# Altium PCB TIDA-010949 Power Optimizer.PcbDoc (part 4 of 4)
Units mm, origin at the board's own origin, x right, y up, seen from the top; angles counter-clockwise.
Board outline 129.4 x 84 mm, 4 copper layers (Power1, Ground1, Ground2, Power2), stack 1.926 mm thick; 265 components, 128 nets, 802 pads, 1069 vias.
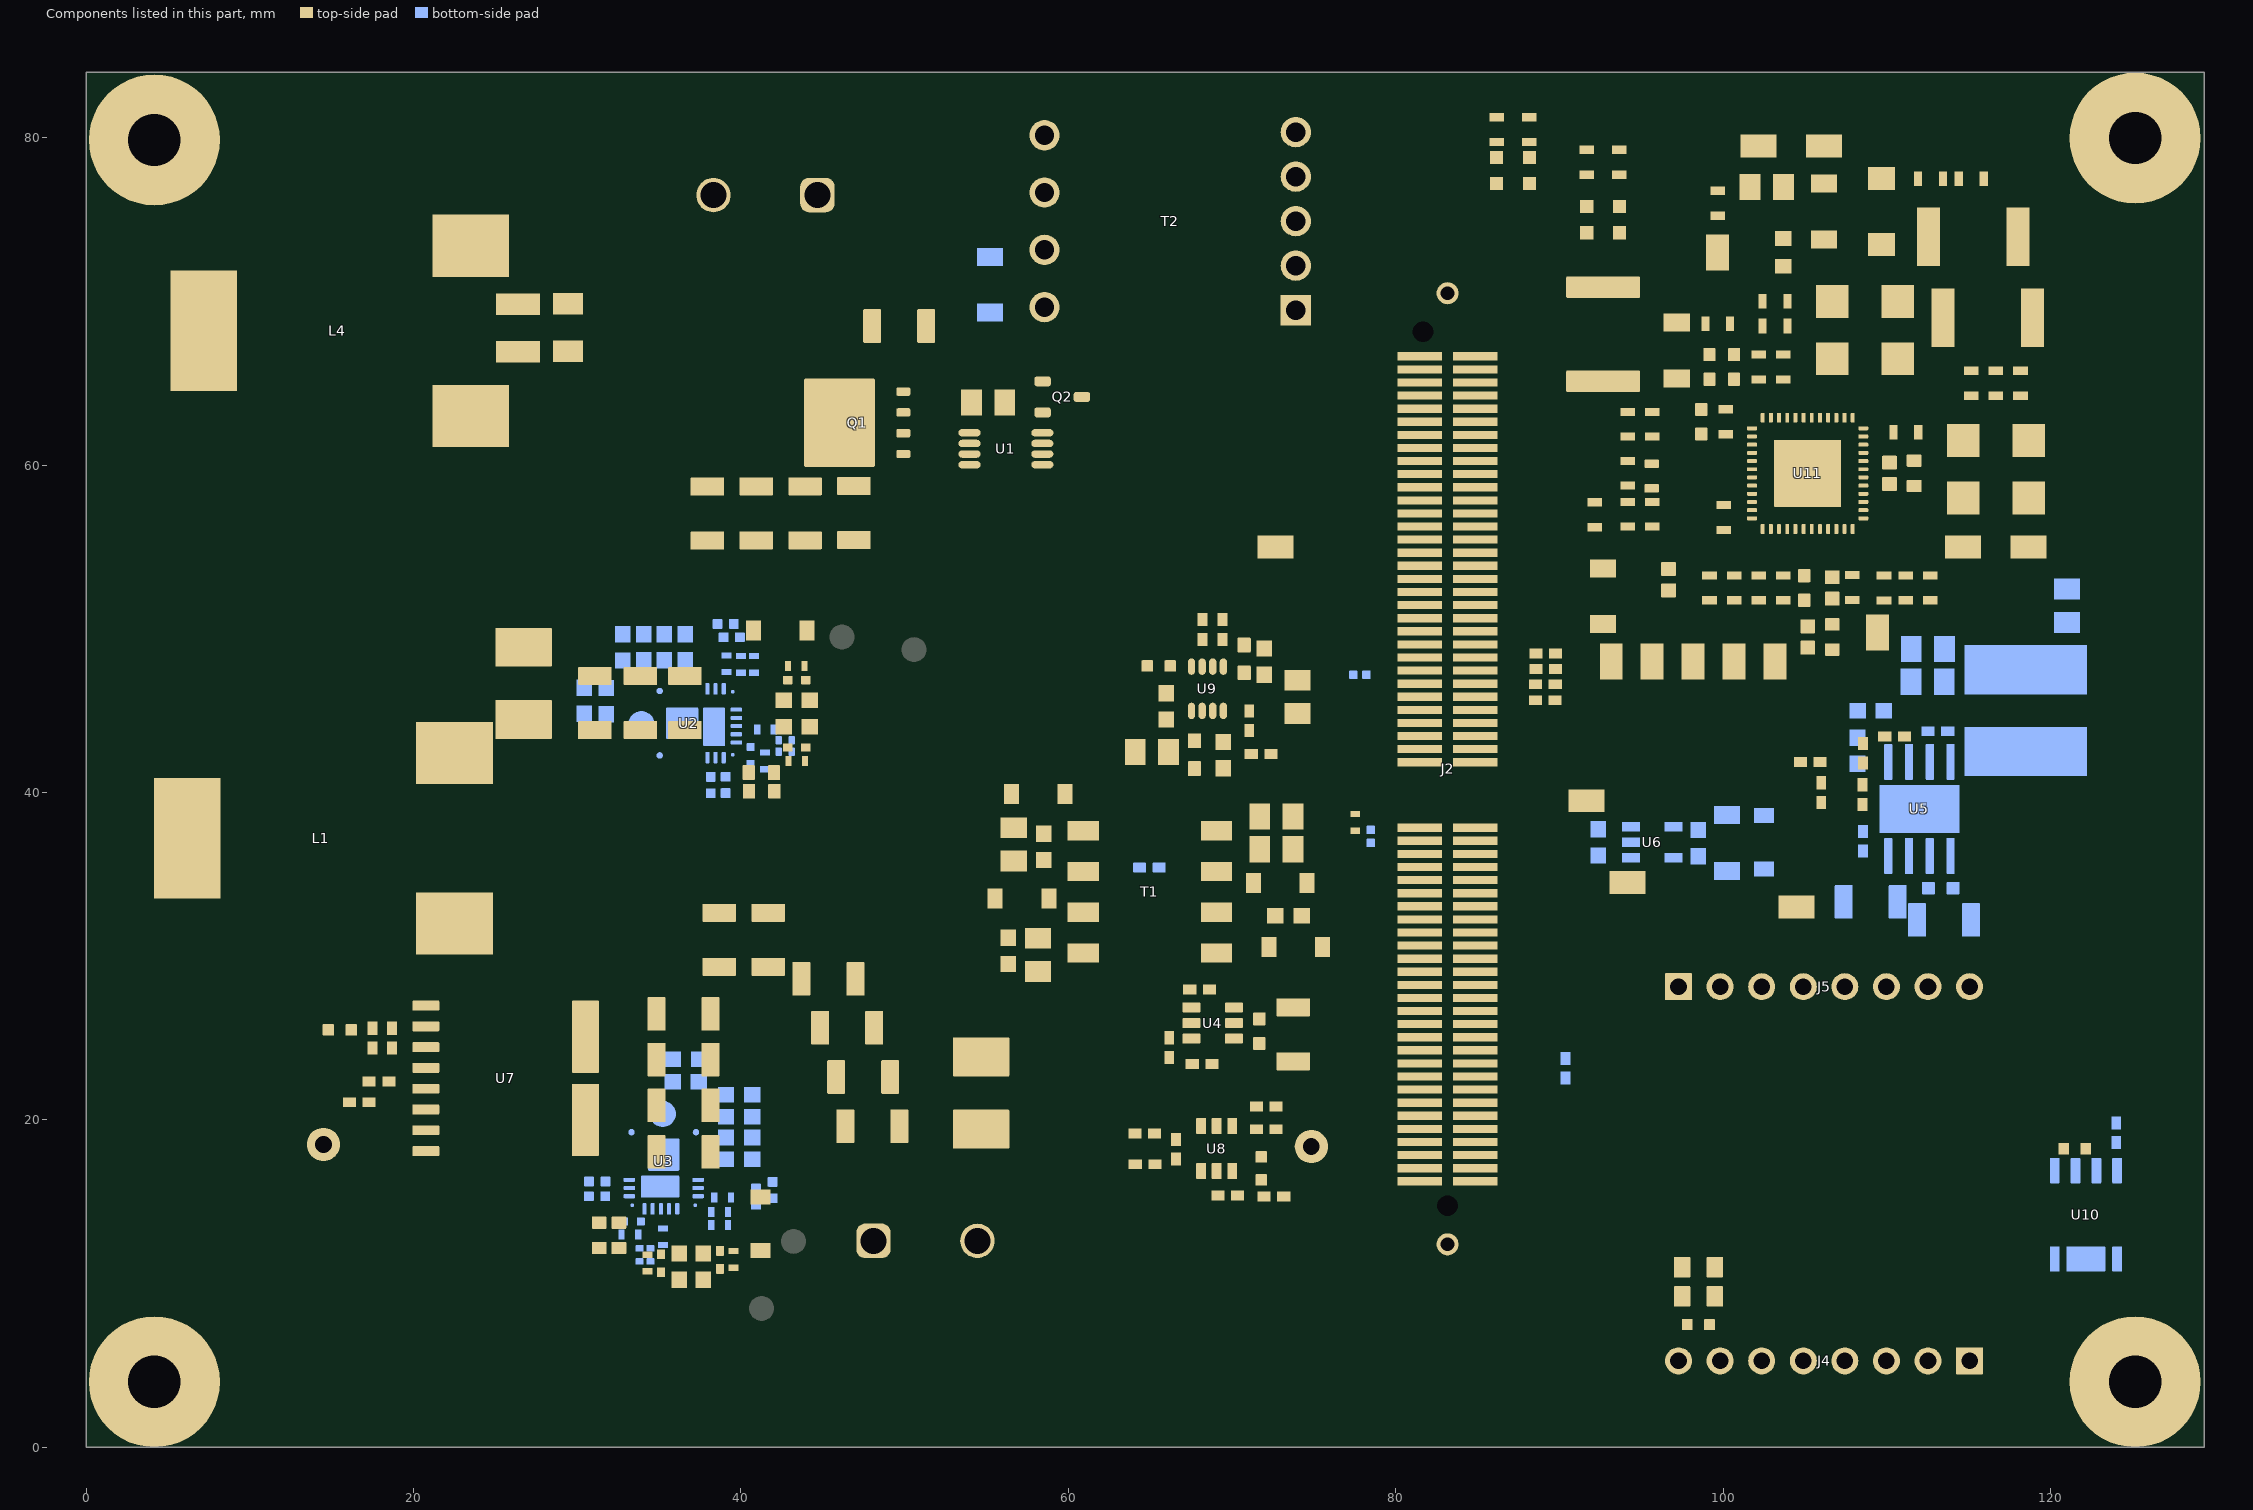
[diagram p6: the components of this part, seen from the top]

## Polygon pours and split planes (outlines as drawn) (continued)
PGND on Power1 "NONET_L-01_P-001" (solid, pour order 88): 38.861,43.047 39.174,42.735 39.174,39 41.174,37 41.174,34.5 38.081,31.408 36.246,31.408 36.246,27.351 34.322,27.351 33.174,28.5 33.174,37.5 37.579,41.905 37.579,43.047
VCC-3V3 on Power1 "NONET_L-01_P-001" (solid, pour order 131): 98.858,11.753 100.794,11.753 100.794,4.391 98.858,4.391
GND on Power1 "NONET_L-01_P-001" (solid, pour order 130): 98.15,11.725 98.15,4.393 96.155,4.393 96.155,11.725
String_PGND on Power1 "NONET_L-01_P-001" (solid, pour order 127): 25.13,69.089 30.593,69.089 31.388,69.884 31.388,71.454 24.546,71.454 24.5,71.5 24.5,69.719
PGND on Power1 "NONET_L-01_P-001" (solid, pour order 126): 25.401,67.58 30.291,67.58 30.414,67.457 30.414,64.361 29.969,63.916 25.14,63.916 24.45,64.606 24.45,67.58
GND on Power1 "NONET_L-01_P-001" (solid, pour order 125): 19.5,27.5 21.5,27.5 22.5,26.5 22.5,17.5 22,17 20.218,17 19.5,17.718
BOOST_SW on Power1 "NONET_L-01_P-001" (solid, pour order 124): 36.865,42.5 36.918,42.447 36.918,41.856 34.777,39.715 29.714,39.715 27.397,39.715 27.397,42.801 27.628,43.033 28.467,43.033 29,42.5
BOOST_SW on Power1 "NONET_L-01_P-001" (solid, pour order 122): 20.5,45.5 28.248,45.5 28.449,45.299 28.449,40.768 27.397,39.715 20.091,39.715 19.336,40.47 19.336,44.336
VOUT on Power1 "NONET_L-01_P-001" (solid, pour order 6): 38.061,46.49 37.55,45.98 30.484,45.98 28.894,47.57 20.93,47.57 19.5,49 19.5,56 20.793,57.293 28.217,57.293 36.424,65.5 42.11,71.187 42.11,80.345 49.831,80.345 49.831,71.298 49.831,65.912 48.535,64.615 48.535,57.634 48.194,57.293 36.733,57.293 36.174,56.734 36.174,52.484 38.061,50.596
PGND on Power1 "NONET_L-01_P-001" (solid, pour order 87): 28.187,65.616 28.593,65.211 28.593,60.114 27.443,58.965 18.334,58.965 17.81,59.489 17.81,64.81 18.616,65.616
SW1 on Power1 "NONET_L-01_P-001" (solid, pour order 113): 29.674,22.166 32.834,22.166 33.512,21.488 33.512,17.494 33.121,17.104 29.621,17.104 29.304,17.421 29.304,21.796
SW2 on Power1 "NONET_L-01_P-001" (solid, pour order 111): 20.555,34.055 24.992,34.055 31.5,27.548 31.5,23.169 31.331,23 29.463,23 22.527,29.936 20.279,29.936 20,30.215 20,33.5
PGND on Power1 "NONET_L-01_P-001" (solid, pour order 84): 49.492,64 51.674,64 52.174,63.5 52.174,61 52.918,60.256 54.754,60.256 55.174,59.836 55.174,55 53.674,53.5 37.174,53.5 36.174,54.5 36.174,56.734 36.736,57.297 48.21,57.297 48.21,57.309 48.674,57.772 48.674,63.181
VIN+ on Power1 "NONET_L-01_P-001" (solid, pour order 0): 45.652,9.848 50.291,9.848 50.674,10.231 50.674,15.85 48.174,18.35 48.174,21 47.674,21.5 47.674,23.5 46.674,24.5 46.674,26.5 45.174,28 45.174,29.5 43.674,31 37.174,31 37.024,30.85 37.024,16.844 37.719,16.149 42.627,16.149 44.866,13.909 44.866,10.634
PV_PGND on Power1 "NONET_L-01_P-001" (solid, pour order 9): 53.078,20.59 53.087,20.599 57.045,20.599 58.135,19.509 58.135,12.735 55.261,9.86 52.033,9.86 51.561,10.332 51.561,19.071 53.085,20.594
GND on Power1 "NONET_L-01_P-001" (solid, pour order 86): 108.954,61.028 106.367,61.028 105.629,61.766 105.629,63.295 106.109,63.775 108.846,63.775 109.417,63.204 109.417,61.49 108.957,61.03
GND on Power1 "NONET_L-01_P-001" (solid, pour order 85): 71.174,25.5 74.174,25.5 75.174,26.5 75.174,28 73.174,30 73.174,34.201 74.969,35.997 74.969,39.704 74.674,40 73.174,40 72.674,39.5 72.674,34.687 71.174,33.187 71.174,29.5
PGND on Power1 "NONET_L-01_P-001" (solid, pour order 83): 56.174,71.5 56.674,71 56.674,67.5 56.174,67 49.824,67 49.674,67.15 49.674,71 50.174,71.5
Vafe on Power1 "NONET_L-01_P-001" (solid, pour order 58): 69.721,26.282 69.729,26.289 70.62,26.289 70.919,25.99 70.919,25.306 71.119,25.107 72.025,25.107 72.762,24.369 75.277,24.369 75.277,22.979 71.15,22.979 69.468,24.661 69.468,26.026 69.719,26.276
Vafe on Power1 "NONET_L-01_P-001" (solid, pour order 70): 89.44,64.477 88.835,65.082 88.835,65.716 89.382,66.264 97.632,66.264 98.209,65.688 104.063,65.688 104.163,65.587 104.163,64.816 103.851,64.504
NetD9_2 on Power1 "NONET_L-01_P-001" (solid, pour order 68): 107.6,65.38 107.571,65.38 105.696,65.38 105.541,65.535 105.541,67.565 105.135,67.971 103.704,67.971 103.569,68.106 103.569,71.277 103.124,71.722 99.161,71.722 98.89,71.993 98.89,72.031 98.89,73.752 99.257,74.119 100.572,74.119 102.061,72.631 104.188,72.631 105.773,71.045 107.784,71.045 107.958,70.871 107.958,65.709 107.629,65.38
NetC50_1 on Power1 "NONET_L-01_P-001" (solid, pour order 60): 68.014,33.828 71.815,33.828 72.412,34.425 72.412,39.334 72.135,39.611 68.014,39.611
VCC_5V on Power1 "NONET_L-01_P-001" (solid, pour order 59): 74.711,29.942 75.431,29.942 75.622,30.133 75.622,34.585 75.041,35.165 74.138,35.165 73.763,34.79 73.763,30.199 74.006,29.957
NetC46_1 on Power1 "NONET_L-01_P-001" (solid, pour order 57): 68.305,30.863 68.378,30.936 70.248,30.936 70.802,30.382 70.802,26.715 70.614,26.527 69.6,26.527 69.256,26.872 69.256,27.377 69.02,27.613 68.274,27.613 68.197,27.689 68.197,29.41 68.064,29.544 68.064,30.648
ISO1_GND on Power1 "NONET_L-01_P-001" (solid, pour order 52): 56.174,30 59.171,30 60.11,30.938 61.737,30.938 62.05,30.625 62.05,28.607 61.549,28.106 56.088,28.106 55.477,28.716 55.477,29.655 55.806,29.984
ISO1_5V on Power1 "NONET_L-01_P-001" (solid, pour order 51): 55.18,34.272 56.291,34.272 56.917,33.646 56.917,32.722 57.668,31.971 58.92,31.971 59.265,31.627 59.265,30.688 58.952,30.375 56.964,30.375 56.714,30.625 55.509,30.625 54.805,31.33 54.805,33.896
ISO2_5V on Power1 "NONET_L-01_P-001" (solid, pour order 49): 56.039,40.608 57.163,40.608 59.164,38.607 59.164,37.143 58.896,36.875 55.874,36.875 55.544,37.205 55.544,40.113
ISO2_GND on Power1 "NONET_L-01_P-001" (solid, pour order 50): 55.966,36.446 59.098,36.446 59.507,36.037 61.664,36.037 61.989,35.712 61.989,34.578 61.813,34.401 59.963,34.401 59.498,34.866 55.817,34.866 55.436,35.247 55.436,36.227 55.653,36.445
NetC67_1 on Power1 "NONET_L-01_P-001" (solid, pour order 39): 69.934,17.302 69.998,17.365 70.714,17.365 71.352,16.726 72.174,16.726 72.384,16.515 72.384,14.999 72.293,14.908 70.026,14.908 69.878,15.055 69.878,16.087 69.703,16.263 69.703,17.187 69.815,17.299
PGND on Power1 "NONET_L-01_P-001" (solid, pour order 36): 36.246,27.715 36.246,15.34 36.161,15.254 33.888,15.254 33.848,15.295 33.848,16.547 34.274,16.972 34.274,27.664 34.411,27.801 36.16,27.801
PGND on Power1 "NONET_L-01_P-001" (solid, pour order 33): 29.507,45.198 38.977,45.198 39.028,45.147 39.028,42.874 38.988,42.834 37.735,42.834 37.31,43.26 29.579,43.26 29.421,43.418 29.421,45.112
String_PGND on Power1 "NONET_L-01_P-001" (solid, pour order 8): 40.674,71 40.674,83.5 0,83.5 0,71
VIN+ on Power2 "NONET_L-01_P-001" (solid, pour order 32): 45.657,9.843 50.286,9.843 50.677,10.234 50.677,15.844 48.177,18.344 48.177,20.994 47.677,21.494 47.677,23.494 46.677,24.494 46.677,26.494 45.177,27.994 45.177,29.494 43.677,30.994 37.177,30.994 37.018,30.836 37.018,16.848 37.724,16.142 42.631,16.142 44.924,13.849 44.924,10.576
Vafe on Power2 "NONET_L-01_P-001" (solid, pour order 92): 124.328,46 127.5,46 127.5,65.217 121.94,70.776 89.847,70.776 88.674,69.603 88.674,65.244 89.441,64.477 121.697,64.477 124.328,61.845
VOUT on Power2 "NONET_L-01_P-001" (solid, pour order 31): 38.032,46.45 37.558,45.975 29.993,45.975 28.399,47.57 20.895,47.57 19.5,48.964 19.5,56 20.797,57.297 28.233,57.297 36.44,65.504 42.119,71.183 42.119,80.348 49.847,80.348 49.847,71.301 49.847,65.915 48.551,64.619 48.551,57.637 48.21,57.297 36.748,57.297 36.174,56.722 36.174,52.503 38.032,50.644
NetC53_1 on Power2 "NONET_L-01_P-001" (solid, pour order 138): 114,44 122,44 122.009,43.991 122.009,41.013 114.303,41.013 114.09,40.8 113.709,40.8 113.702,40.808 113.702,43.224 113.479,43.447 113.479,44.047
Vafe on Power2 "NONET_L-01_P-001" (solid, pour order 137): 124.422,51 124.422,46 112.886,46 112.886,51
VIN+ on Power2 "NONET_L-01_P-001" (solid, pour order 136): 112.81,37.2 112.939,37.071 112.939,31.754 112.31,31.126 111.04,31.126 110.064,32.101 110.064,34.267 110.207,34.41 110.953,34.41 111.092,34.55 111.092,37.112 111.18,37.2
BOOST_SW on Power2 "NONET_L-01_P-001" (solid, pour order 123): 36.865,42.5 36.918,42.447 36.918,41.856 34.777,39.715 29.714,39.715 27.397,39.715 27.397,42.801 27.628,43.033 28.467,43.033 29,42.5
BOOST_SW on Power2 "NONET_L-01_P-001" (solid, pour order 121): 20.5,45.5 28.248,45.5 28.449,45.299 28.449,40.768 27.397,39.715 20.091,39.715 19.336,40.47 19.336,44.336
PGND on Power2 "NONET_L-01_P-001" (solid, pour order 120): 28.187,65.616 28.593,65.211 28.593,60.114 27.443,58.965 18.334,58.965 17.81,59.489 17.81,64.81 18.616,65.616
SW1 on Power2 "NONET_L-01_P-001" (solid, pour order 114): 29.674,22.166 32.525,22.166 33.512,21.179 33.512,17.494 33.121,17.104 29.621,17.104 29.304,17.421 29.304,21.796
SW2 on Power2 "NONET_L-01_P-001" (solid, pour order 112): 20.529,34.135 24.966,34.135 31.474,27.627 31.474,23.248 31.304,23.079 29.436,23.079 22.501,30.015 20.253,30.015 19.974,30.294 19.974,33.579
PGND on Power2 "NONET_L-01_P-001" (solid, pour order 95): 34.322,27.351 33.437,28.237 33.437,31.027 39.392,36.982 47.174,36.982 47.174,34 44.969,31.795 36.489,31.795 36.246,31.552 36.246,27.351
PV_PGND on Power2 "NONET_L-01_P-001" (solid, pour order 27): 53.078,20.59 53.087,20.599 57.045,20.599 58.224,19.42 58.224,12.823 54.761,9.36 52.14,9.36 51.561,9.939 51.561,19.071 53.085,20.594
amb_tmp on Power2 "NONET_L-01_P-001" (solid, pour order 94): 119.155,12.369 129.162,12.369 129.162,0.249 119.155,0.249
GND on Power2 "NONET_L-01_P-001" (solid, pour order 89): 103.144,61.449 107.144,61.449 107.144,57.5 103.144,57.5
PGND on Power2 "NONET_L-01_P-001" (solid, pour order 30): 32.258,49.167 32.146,49.279 32.146,50.11 32.448,50.411 36.949,50.411 37.293,50.067 37.293,49.279 37.181,49.167
PGND on Power2 "NONET_L-01_P-001" (solid, pour order 29): 40.197,22.038 40.289,22.131 41.17,22.131 41.48,21.821 41.48,17.135 41.299,16.955 40.368,16.955 40.197,17.127
PGND on Power2 "NONET_L-01_P-001" (solid, pour order 82): 56.174,71.5 56.674,71 56.674,67.59 56.084,67 50.674,67 50.174,67.5 50.174,71 50.674,71.5
PGND on Power2 "NONET_L-01_P-001" (solid, pour order 81): 36.452,57 47.674,57 50.959,60.286 55.888,60.286 57.674,58.5 57.674,54.5 56.674,53.5 36.674,53.5 36.174,54 36.174,56.722
PGND on Power2 "NONET_L-01_P-001" (solid, pour order 79): 49.487,63.995 49.492,64 52.174,64 52.674,63.5 52.674,58.5 52.174,58 49.174,58 48.674,58.5 48.674,63.5 49.174,64
PGND on Power2 "NONET_L-01_P-001" (solid, pour order 78): 49.1,18 50.674,18 51.674,19 51.674,22 52.342,22.668 58.594,22.668 59.304,23.379 59.304,36.4 58.704,37 46.674,37 44.174,34.5 44.174,31.077 45.581,29.669 45.581,28.169 47.081,26.669 47.081,24.625 48.081,23.625 48.081,21.5 48.581,21 48.581,18.519
VCC-3V3 on Power2 "NONET_L-01_P-001" (solid, pour order 54): 96.718,36.634 103.835,36.634 104.163,36.306 104.163,33.989 103.762,33.589 96.585,33.589 96.258,33.915 96.258,36.174
GND on Power2 "NONET_L-01_P-001" (solid, pour order 55): 97.644,37.159 103.977,37.159 104.319,37.501 104.319,39.278 103.984,39.613 96.839,39.613 96.31,39.085 96.31,37.738 96.89,37.159
PGND on Power2 "NONET_L-01_P-001" (solid, pour order 35): 36.242,27.716 36.242,15.33 36.162,15.25 33.889,15.25 33.849,15.29 33.849,16.543 34.275,16.968 34.275,27.66 34.411,27.797 36.161,27.797
PGND on Power2 "NONET_L-01_P-001" (solid, pour order 34): 29.504,45.189 38.992,45.189 39.034,45.147 39.034,42.875 38.994,42.834 37.742,42.834 37.316,43.26 29.585,43.26 29.427,43.418 29.427,45.112
String_PGND on Power2 "NONET_L-01_P-001" (solid, pour order 11): 40.674,71 40.674,83.5 0,83.5 0,71
GND on Ground1 "NONET_L-01_P-001" (solid, pour order 74): 18.174,16.5 33.555,16.5 33.555,14.951 36.721,14.951 40.055,11.476 47.531,4 64.674,4 66.174,5.5 66.174,22.97 65.174,23.97 65.174,38.5 62.674,41 45.674,41 43.174,38.5 40.463,38.5 39.328,39.77 39.328,42.467 39.328,45.116 42.212,48 66.674,48 71.389,52.716 71.389,83.5 129.401,83.5 129.401,0.5 19.277,0.5 18.174,1.604
PGND on Ground1 "NONET_L-01_P-001" (solid, pour order 133): 0.018,83.647 71.518,83.647 72.018,83.147 72.018,3.647 68.518,0.147 -0.482,0.147
BOOST_SW on Ground1 "NONET_L-01_P-001" (solid, pour order 132): 31.5,42.5 36.855,42.5 36.92,42.435 36.918,42.433 36.918,41.838 34.804,39.724 31.276,39.724 31,40 31,42
GND on Ground1 "NONET_L-01_P-001" (solid, pour order 117): 11.5,27 18.631,27 19.273,27.642 21.525,27.642 22.527,26.64 22.527,2.527 20.5,0.5 11.5,0.5
SW1 on Ground1 "NONET_L-01_P-001" (solid, pour order 115): 29.674,22.166 32.834,22.166 33.512,21.488 33.512,17.494 33.121,17.104 29.621,17.104 29.304,17.421 29.304,21.796
VCC-3V3 on Ground2 "NONET_L-01_P-001" (solid, pour order 93): 90.071,71 120.174,71 122.174,69 122.174,54.5 120.174,52.5 89.174,52.5 87.674,54 87.674,68.603
PGND on Ground2 "NONET_L-01_P-001" (solid, pour order 135): 1,84 71.094,84 71.094,2.094 69.5,0.5 0.5,0.5
BOOST_SW on Ground2 "NONET_L-01_P-001" (solid, pour order 134): 31.5,42.5 36.818,42.5 36.885,42.433 36.918,42.433 36.918,41.838 34.804,39.724 31.276,39.724 31,40 31,42
SW1 on Ground2 "NONET_L-01_P-001" (solid, pour order 116): 29.674,22.166 32.834,22.166 33.512,21.488 33.512,17.494 33.121,17.104 29.621,17.104 29.304,17.421 29.304,21.796
ISO1_GND on Ground2 "NONET_L-01_P-001" (solid, pour order 97): 37,14.952 37,16.5 42.273,16.5 42.789,15.984 42.789,11.733 42.275,11.219 39.946,11.219 37.002,14.163
ISO2_GND on Ground2 "NONET_L-01_P-001" (solid, pour order 96): 37.824,45.953 37.824,50.325 38.659,51.16 44.204,51.16 44.77,50.594 44.77,49.643 41.08,45.953
no net on Top Solder "NONET_L-01_P-001" (solid): 30.016,44.927 38.412,44.927 38.412,44.926 38.412,43.274 30.016,43.274
no net on Top Solder "NONET_L-01_P-001" (solid): 38.676,27.5 44.176,27.5 44.176,19 38.676,19
no net on Top Solder "NONET_L-01_P-001" (solid): 35.674,15.288 34.312,15.288 34.312,32 35.674,32 35.674,18
no net on Top Solder "NONET_L-01_P-001" (solid): 43.924,67.5 47.674,67.5 47.674,65.5 43.924,65.5
no net on Top Solder "NONET_L-01_P-001" (solid): 40.674,65.75 43.174,65.75 43.174,60.25 40.674,60.25
no net on Top Solder "NONET_L-01_P-001" (solid): 38.174,29.5 43.674,29.5 43.674,27.5 38.174,27.5
no net on Bottom Solder "NONET_L-01_P-001" (solid): 103.144,61.449 107.144,61.449 107.144,57.706 103.144,57.706
no net on Bottom Solder "NONET_L-01_P-001" (solid): 38.719,43.261 30.174,43.261 30.174,45.112 38.474,45.112 38.694,44.892
no net on Bottom Solder "NONET_L-01_P-001" (solid): 56.174,20.251 53.174,20.251 53.174,18.331 56.174,18.331
no net on Bottom Solder "NONET_L-01_P-001" (solid): 36.174,82.181 11.674,82.181 11.674,71.5 36.174,71.5
no net on Bottom Solder "NONET_L-01_P-001" (solid): 53.174,23.014 56.174,23.014 56.174,24.943 53.174,24.943
no net on Bottom Solder "NONET_L-01_P-001" (solid): 33.954,16.53 33.954,16.647 34.339,17.032 34.339,27.724 34.411,27.797 36.161,27.797 36.221,27.737 36.221,15.337 36.172,15.288 34.009,15.288 33.973,15.324
no net on Bottom Solder "NONET_L-01_P-001" (solid): 41.596,25.827 39.596,25.827 39.596,24.327 41.596,24.327
no net on Bottom Solder "NONET_L-01_P-001" (solid): 41.603,28.15 39.603,28.15 39.603,26.65 41.603,26.65
no net on Bottom Solder "NONET_L-01_P-001" (solid): 46.174,20.75 44.174,20.75 44.174,19.25 46.174,19.25
no net on Bottom Solder "NONET_L-01_P-001" (solid): 46.758,18.694 44.758,18.694 44.758,17.194 46.758,17.194
no net on Bottom Solder "NONET_L-01_P-001" (solid): 45.674,23 43.674,23 43.674,21.5 45.674,21.5
no net on Bottom Solder "NONET_L-01_P-001" (solid): 44.624,27.334 42.624,27.334 42.624,25.834 44.624,25.834
no net on Bottom Solder "NONET_L-01_P-001" (solid): 45.176,25.25 43.176,25.25 43.176,23.75 45.176,23.75

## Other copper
Power1:
  pour cut-out: 36.369,38.078 37.038,38.747 37.944,38.747 38.558,38.132 38.558,37.223 37.962,36.626 36.895,36.626 36.369,37.152
  pour cut-out: 35.104,34.466 35.637,35 36.698,35 37.182,34.515 37.182,33.544 36.627,32.989 35.644,32.989 35.104,33.529
  pour cut-out: 0,0 0,9.5 9.5,9.5 9.5,0
  pour cut-out: 0,74.5 0,84 9.5,84 9.5,74.5
Ground1:
  pour cut-out: 35.104,34.466 35.637,35 36.698,35 37.182,34.515 37.182,33.544 36.627,32.989 35.644,32.989 35.104,33.529
  pour cut-out: 0,0 0,9.5 9.5,9.5 9.5,0
  pour cut-out: 0,74.5 0,84 9.5,84 9.5,74.5
  pour cut-out: 120,75 120,84 129.5,84 129.5,75
  pour cut-out: 118.095,0.5 118.095,14 129,14 129,0.5
  pour cut-out: 36.369,38.078 37.038,38.747 37.944,38.747 38.558,38.132 38.558,37.223 37.962,36.626 36.973,36.626 36.369,37.23
Ground2:
  pour cut-out: 0,0 0,9.5 9.5,9.5 9.5,0
  pour cut-out: 0,74.5 0,84 9.5,84 9.5,74.5
  pour cut-out: 36.369,38.078 37.038,38.747 37.944,38.747 38.558,38.132 38.558,37.223 37.962,36.626 36.973,36.626 36.369,37.23
  pour cut-out: 35.104,34.466 35.637,35 36.698,35 37.182,34.515 37.182,33.544 36.627,32.989 35.644,32.989 35.104,33.529
Power2:
  pour cut-out: 36.369,38.078 37.038,38.747 37.944,38.747 38.558,38.132 38.558,37.223 37.962,36.626 36.973,36.626 36.369,37.23
  pour cut-out: 31.896,48.766 32.095,48.566 37.441,48.566 37.443,48.569 37.443,48.774
  pour cut-out: 39.795,22.422 39.592,22.219 39.592,16.79 39.6,16.782 39.795,16.782
  pour cut-out: 35.104,34.466 35.637,35 36.568,35 37.182,34.386 37.182,33.544 36.627,32.989 35.644,32.989 35.104,33.529
  pour cut-out: 0,0 0,9.5 9.5,9.5 9.5,0
  pour cut-out: 0,74.5 0,84 9.5,84 9.5,74.5

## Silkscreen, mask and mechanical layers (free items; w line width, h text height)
Top Overlay:
  text "S_PGND" at 29.635,75.777 h0.85
  text "VOUT" at 48.635,75.635 h0.85
  text "GND" at 71.919,57.074 h0.7
  text "BOOST_SW" at 28.094,37.894 h0.52
  text "GND" at 90.737,37.46 h0.7
  text "PGND" at 34.457,36.566 h0.52
  text "PGND" at 32.987,34.147 h0.52
  text "BUCK_SW" at 27.326,32.395 h0.52
  text "5V" at 93.63,31.63 h0.7
  text "3.3V" at 103.564,30.372 h0.7
  text "I_in" at 73.936,16.054 h0.7
  text "I_inductor" at 13.63,14.747 h0.7
  text "TIDA-010949" at 15.754,6.254 h1.52
  text "P_PGND" at 58.142,5.284 h0.85
  text "VIN+" at 41.642,5.142 h0.85
M1 Board Outline:
  the board outline again, w0.254
M2 Board Dimensions:
  rectangle: -48.826,-30.842 -45.651,-27.667
  rectangle: -45.651,-34.017 -36.126,-30.842
  lines w0.178: -48.826,-30.842 -23.426,-30.842 ; -45.651,-34.017 -45.651,-27.667 ; -42.476,-34.017 -42.476,-27.667 ; -36.126,-34.017 -36.126,-27.667 ; -29.776,-34.017 -29.776,-27.667 ; -48.826,-34.017 -23.426,-34.017 -23.426,-27.667 -48.826,-27.667 -48.826,-34.017
M5 Assembly Top:
  lines w0.254: -56.243,-47.483 111.397,-47.483 ; -56.243,-42.319 111.448,-42.319 ; -56.243,-37.154 -56.243,-52.648 45.484,-52.648 111.448,-52.648 111.448,-37.154 -56.231,-37.154 -56.231,-52.648 -16.213,-52.648 ; 6.368,-52.648 6.368,-37.154 ; 38.55,-42.319 38.55,-37.154 ; 59.886,-42.319 59.886,-37.154 ; 75.684,-52.813 75.684,-47.661
  text "COMPONENTS MARKED 'DNP' SHOULD NOT BE POPULATED." at -19.528,-31.947 h1.52
  text "ASSEMBLY VARIANT:" at -19.54,-34.881 h1.52
  text ".VariantName" at 6.774,-34.881 h1.52
  text "PCB VIEWED FROM TOP SIDE" at -54.63,-40.511 h1.52
  text "BOARD #:" at 8.273,-40.511 h1.52
  text ".PRJ_Number" at 22.128,-40.511 h1.52
  text "REV:" at 43.579,-40.511 h1.52
  text ".PCB_Rev" at 50.983,-40.511 h1.52
  text "SVN REV:" at 64.864,-40.511 h1.52
  text ".VersionControl_RevNumber" at 77.716,-40.511 h1.52
  text "TID #:" at 8.273,-45.676 h1.52
  text ".TID" at 22.128,-45.676 h1.52
  text "PLOT NAME =" at -54.63,-50.891 h1.52
  text ".plot_File_Name" at -34.171,-50.891 h1.52
  text "GENERATED    :" at 8.324,-50.891 h1.52
  text ".Print_Date" at 30.409,-50.891 h1.52
  text ".Print_Time" at 48.925,-50.891 h1.52
  text "TEXAS INSTRUMENTS" at 81.044,-50.891 h1.52
M6 Assembly Bottom:
  lines w0.254: -56.256,-42.331 111.435,-42.331 ; -56.205,-47.496 111.435,-47.496 ; -20.493,-52.826 -20.493,-47.674 ; -4.694,-42.331 -4.694,-37.167 ; 16.642,-42.331 16.642,-37.167 ; 48.824,-52.661 48.824,-37.167 ; 71.404,-52.661 111.422,-52.661 111.422,-37.167 -56.256,-37.167 -56.256,-52.661 9.708,-52.661 111.435,-52.661 111.435,-37.167
  text "COMPONENTS MARKED 'DNP' SHOULD NOT BE POPULATED." at 106.164,-31.934 h1.52
  text ".VariantName" at 79.647,-34.881 h1.52
  text "ASSEMBLY VARIANT:" at 106.037,-34.881 h1.52
  text ".VersionControl_RevNumber" at -22.525,-40.524 h1.52
  text "SVN REV:" at -9.672,-40.524 h1.52
  text ".PCB_Rev" at 4.209,-40.524 h1.52
  text "REV:" at 11.613,-40.524 h1.52
  text ".PRJ_Number" at 33.063,-40.524 h1.52
  text "BOARD #:" at 46.919,-40.524 h1.52
  text "PCB VIEWED FROM BOTTOM SIDE" at 109.822,-40.524 h1.52
  text ".TID" at 33.063,-45.688 h1.52
  text "TID #:" at 46.919,-45.688 h1.52
  text "TEXAS INSTRUMENTS" at -25.852,-50.904 h1.52
  text ".Print_Time" at 6.266,-50.904 h1.52
  text ".Print_Date" at 24.783,-50.904 h1.52
  text "GENERATED    :" at 46.868,-50.904 h1.52
  text ".plot_File_Name" at 89.362,-50.904 h1.52
  text "PLOT NAME =" at 109.822,-50.904 h1.52
M9 Title Sheet:
  drawing of 57 lines, arcs and shapes, not listed
  text "1" at -30.035,180.27 h1.78
  text "2" at 33.355,180.27 h1.78
  text "3" at 96.585,180.27 h1.78
  text "4" at 160.254,180.27 h1.78
  text "5" at 223.728,180.27 h1.78
  text "6" at 287.355,180.27 h1.78
  text "A" at -59.406,151.238 h1.78
  text "A" at 316.514,151.238 h1.78
  text "B" at -59.406,90.786 h1.78
  text "B" at 316.514,90.786 h1.78
  text "C" at -59.406,30.461 h1.78
  text "C" at 316.514,30.461 h1.78
  text "PROJECT TITLE:" at 239.298,-16.809 h1.14
  text ".PRJ_Title" at 240.568,-20.195 h1.78
  text "DESIGNED FOR:" at 239.298,-24.454 h1.14
  text ".PRJ_Customer" at 240.568,-28.01 h1.78
  text "D" at -59.406,-29.737 h1.78
  text "D" at 316.514,-29.737 h1.78
  text "FILE NAME:" at 239.298,-32.074 h1.14
  text ".PCB_File_Name_No_Path" at 240.568,-35.122 h1.78
  text "Texas Instruments (TI) and/or its licensors do not warrant the accuracy or completeness of this specification" at 113.073,-39.233 h1.14
  text "ENGINEER:" at 239.298,-39.44 h1.14
  text "LAYOUT BY:" at 277.525,-39.44 h1.14
  text "or any information contained therein. TI and/or its licensors do not warrant that this design will meet" at 111.931,-42.094 h1.14
  text ".PRJ_Engineer" at 240.568,-43.377 h1.78
  text ".PCB_Layout" at 278.808,-43.377 h1.78
  text "the specifications, will be suitable for your application or fit for any particular purpose, or will operate in" at 111.931,-44.956 h1.14
  text ".Layer_Name" at -34.171,-45.663 h1.52
  text "ALTIUM DESIGNER VERSION:" at 277.525,-47.314 h1.14
  text "an implementation. TI and/or its licensors do not warrant that the design is production worthy. You should" at 111.931,-47.818 h1.14
  text "completely validate and test your design implementation to confirm the system functionality for your application." at 113.073,-50.68 h1.14
  text ".print_Scale" at 240.568,-50.701 h1.78
  text ".Application_BuildNumber" at 278.808,-50.701 h1.78
  text "1" at -30.035,-55.95 h1.78
  text "2" at 33.355,-55.95 h1.78
  text "3" at 96.585,-55.95 h1.78
  text "4" at 160.254,-55.95 h1.78
  text "5" at 223.728,-55.95 h1.78
  text "6" at 287.355,-55.95 h1.78
M10 Fab Notes:
  drawing of 189 lines, arcs and shapes, not listed
  text "DESIGN INFORMATION" at 265.677,137.59 h1.52
  text "MIN. TRACK WIDTH:" at 249.305,134.234 h1.52
  text "8" at 277.15,134.234 h1.52
  text "MIL" at 281.08,134.234 h1.52
  text "7.874" at 272.924,131.143 h1.52
  text "MIN. CLEARANCE:" at 249.305,131.081 h1.52
  text "MIL" at 281.08,131.081 h1.52
  text "MIN. VIA PAD SIZE:" at 249.305,127.928 h1.52
  text "24" at 276.388,127.928 h1.52
  text "MIL" at 281.08,127.928 h1.52
  text "0.05mm (2MIL)" at 266.958,124.629 h1.52
  text "MINIMUM ANNULAR RING" at 240.943,124.42 h1.52
  text "EXTERNAL" at 284.941,124.42 h1.52
  text "PER" at 246.023,121.623 h1.52
  text "IPC-D-275 CLASS 2 LEVEL C" at 251.611,121.622 h1.52
  text "MIL, HOLES" at 289.412,119.07 h1.52
  text "+/-" at 279.443,118.852 h1.52
  text "+/-" at 301.135,118.852 h1.52
  text "REGISTRATION TOLERANCES:" at 240.943,118.825 h1.52
  text "METAL" at 271.417,118.825 h1.52
  text "5" at 286.052,118.825 h1.52
  text "3" at 307.21,118.825 h1.52
  text "MIL" at 310.163,118.825 h1.52
  text "HOLE SIZE TOLERANCE (UNLESS OTHERWISE SPECIFIED):" at 240.943,116.328 h1.52
  text "+/-" at 301.135,116.255 h1.52
  text "3" at 307.21,116.228 h1.52
  text "MIL" at 310.163,116.228 h1.52
  text "MATERIAL:" at 239.043,112.732 h1.52
  text "FR-4 High Tg" at 264.099,109.467 h1.52
  text "X" at 260.43,109.264 h1.52
  text "FR-4" at 249.737,109.15 h1.52
  text "OTHER" at 287.532,109.15 h1.52
  text "62 MIL (1.6mm) +/-10%" at 257.867,105.517 h1.52
  text "X" at 254.817,105.454 h1.52
  text "THICKNESS:" at 240.943,105.308 h1.52
  text "OTHER" at 290.504,105.308 h1.52
  text "TOLERANCE:" at 240.943,101.795 h1.52
  text "X" at 262.488,101.795 h1.52
  text "ANSI IPC-6012 TYPE 3 CLASS 2" at 267.009,101.795 h1.52
  text "OTHER +/-" at 267.009,98.132 h1.52
  text "BOW & TWIST:" at 240.943,94.444 h1.52
  text "X" at 262.488,94.444 h1.52
  text "ANSI IPC-6012 TYPE 3 CLASS 2" at 267.009,94.444 h1.52
  text "OTHER +/-" at 267.009,90.718 h1.52
  text "DRILLING:" at 239.043,87.401 h1.52
  text "NC_DRILL FILES" at 283.773,84.729 h1.52
  text "REFERENCE:" at 240.943,84.629 h1.52
  text "X" at 257.636,84.626 h1.52
  text "AS SHOWN" at 262.157,84.629 h1.52
  text "X" at 280.522,84.629 h1.52
  text "OTHER" at 291.342,81.016 h1.52
  text "PTH COPPER THICKNESS:" at 240.934,80.926 h1.52
  text "X" at 269.871,80.926 h1.52
  text "20-30 um" at 273.122,80.926 h1.52
  text "BOARD FINISH:" at 239.043,77.177 h1.52
  text "SILKSCREEN:" at 242.986,74.38 h1.52
  text "X" at 267.314,74.38 h1.52
  text "TOP" at 270.285,74.38 h1.52
  text "X" at 280.268,74.38 h1.52
  text "BOTTOM" at 283.265,74.38 h1.52
  text "SILKSCREEN COLOR:" at 242.986,70.438 h1.52
  text "X" at 267.288,70.438 h1.52
  text "WHITE" at 270.285,70.438 h1.52
  text "OTHER" at 283.265,70.438 h1.52
  text "X" at 270.616,66.795 h1.52
  text "GREEN" at 273.613,66.795 h1.52
  text "OTHER" at 289.31,66.795 h1.52
  text "SOLDER RESIST COLOR:" at 242.986,66.62 h1.52
  text "X" at 270.616,62.877 h1.52
  text "MATTE" at 273.613,62.877 h1.52
  text "SEMI-GLOSS" at 289.298,62.86 h1.52
  text "IMMERSION GOLD (ENIG)" at 265.993,58.488 h1.52
  text "ENEPIG" at 299.966,58.305 h1.52
  text "SURFACE FINISH:" at 239.043,58.279 h1.52
  text "X" at 261.472,58.279 h1.52
  text "IMM. TIN/SILVER OR EQUIV" at 247.414,54.791 h1.52
  text "OTHER" at 283.773,54.691 h1.52
  text "ARRAY/PANEL:" at 239.043,50.745 h1.52
  text "CUT AND TRIM PER M1 BOARD OUTLINE" at 265.993,50.536 h1.52
  text "N.C. ROUTE" at 265.993,47.082 h1.52
  text "X" at 283.468,47.082 h1.52
  text "V. SCORE" at 287.989,47.082 h1.52
  text "CERTIFICATION:" at 239.043,43.803 h1.52
  text "MATERIALS AND WORKMANSHIP FOR ALL PCBS" at 257.458,43.803 h1.52
  text "TO MEET OR EXCEED THE REQUIREMENTS OF:" at 257.458,41.413 h1.52
  text "X" at 248.251,38.146 h1.52
  text "ANSI IPC-A-600F CLASS ->" at 251.502,38.146 h1.52
  text "X" at 293.362,38.146 h1.52
  text "2" at 296.155,38.146 h1.52
  text "1" at 288.154,38.108 h1.52
  text "3" at 305.147,38.108 h1.52
  text "X" at 268.876,34.395 h1.52
  text "RoHS" at 272.127,34.395 h1.52
  text "OTHER" at 288.495,34.395 h1.52
  text "PER ORDER" at 298.58,34.395 h1.52
  text "ALL BOARDS MUST MEET OR EXCEED UL94-V0 REQUIREMENTS." at 239.743,30.488 h1.52
  text "PCB MUST BEAR THE UL94V-0 UL REGISTERED MATERIAL ID NUMBER" at 239.743,27.54 h1.52
  text "ADDITIONAL REQUIREMENTS:" at 239.043,23.236 h1.52
  text "MICROSECTION:" at 240.943,20.515 h1.52
  text "YES" at 263.948,20.515 h1.52
  text "REQUIRED" at 285.83,16.849 h1.52
  text "BARE BOARD ELEC. TEST:" at 240.943,16.777 h1.52
  text "NONE" at 274.108,16.777 h1.52
  text "X" at 282.833,16.777 h1.52
  text "PER ORDER" at 300.867,16.777 h1.52
  text "XX MIL VIAS REQUIRE NON-CONDUCTIVE FILL AND PLANARIZE" at 245.214,11.571 h1.5
  text "XX MIL VIAS REQUIRE CONDUCTIVE FILL AND PLANARIZE" at 245.417,8.93 h1.52
  text "OUTER XX MIL TRACES REQUIRE 50 OHM SINGLE-ENDED IMPEDANCE" at 245.392,4.78 h1.47
  text "LAYER 2 & 3 (INNER LAYERS) XX MIL WIDE, XX MIL SPACE / TRACES REQUIRE 100 OHM DIFFERENTIAL IMPEDANCE" at 245.189,-1.207 h1.52
M11 Gerber Information:
  lines w0.254: -56.243,-47.483 111.397,-47.483 ; -56.243,-42.319 111.448,-42.319 ; -56.243,-37.154 -56.243,-52.648 45.484,-52.648 111.448,-52.648 111.448,-37.154 -56.231,-37.154 -56.231,-52.648 -16.213,-52.648 ; 6.368,-52.648 6.368,-37.154 ; 38.55,-42.319 38.55,-37.154 ; 59.886,-42.319 59.886,-37.154 ; 75.684,-52.813 75.684,-47.661
  text "ALL ARTWORK VIEWED FROM TOP SIDE" at -54.63,-40.511 h1.52
  text "BOARD #:" at 8.273,-40.511 h1.52
  text ".PRJ_Number" at 22.128,-40.511 h1.52
  text "REV:" at 43.579,-40.511 h1.52
  text ".PCB_Rev" at 50.983,-40.511 h1.52
  text "SVN REV:" at 64.864,-40.511 h1.52
  text ".VersionControl_RevNumber" at 77.716,-40.511 h1.52
  text "LAYER NAME =" at -54.63,-45.663 h1.52
  text "TID #:" at 8.273,-45.676 h1.52
  text ".TID" at 22.128,-45.676 h1.52
  text "PLOT NAME =" at -54.63,-50.891 h1.52
  text ".plot_File_Name" at -34.171,-50.891 h1.52
  text "GENERATED    :" at 8.324,-50.891 h1.52
  text ".Print_Date" at 30.409,-50.891 h1.52
  text ".Print_Time" at 48.925,-50.891 h1.52
  text "TEXAS INSTRUMENTS" at 81.044,-50.891 h1.52
M12 Stackup:
  drawing of 295 lines, arcs and shapes, not listed
  text "Layer" at 200.642,176.166 h1.52
  text "Name" at 211.054,176.166 h1.52
  text "Material" at 234.669,176.166 h1.52
  text "Thickness" at 256.507,176.166 h1.52
  text "Constant" at 273.013,176.166 h1.52
  text "Board Layer Stack" at 287.488,176.166 h1.52
  text "Top Overlay" at 211.054,173.118 h1.52
  text "Top Solder" at 211.054,170.07 h1.52
  text "Solder Resist" at 234.669,170.07 h1.52
  text "0.40mil" at 256.507,170.07 h1.52
  text "3.5" at 273.013,170.07 h1.52
  text "1" at 200.642,167.022 h1.52
  text "Power1" at 211.054,167.022 h1.52
  text "CF-004" at 234.669,167.022 h1.52
  text "2.76mil" at 256.507,167.022 h1.52
  text "Dielectric 1" at 211.054,163.974 h1.52
  text "PP-006" at 234.669,163.974 h1.52
  text "2.80mil" at 256.507,163.974 h1.52
  text "4.1" at 273.013,163.974 h1.52
  text "2" at 200.642,160.926 h1.52
  text "Ground1" at 211.054,160.926 h1.52
  text "2.76mil" at 256.507,160.926 h1.52
  text "Dielectric1" at 211.054,157.878 h1.52
  text "FR-4 High Tg" at 234.669,157.878 h1.52
  text "59.20mil" at 256.507,157.878 h1.52
  text "4.8" at 273.013,157.878 h1.52
  text "3" at 200.642,154.83 h1.52
  text "Ground2" at 211.054,154.83 h1.52
  text "2.76mil" at 256.507,154.83 h1.52
  text "Dielectric 2" at 211.054,151.782 h1.52
  text "PP-006" at 234.669,151.782 h1.52
  text "2.80mil" at 256.507,151.782 h1.52
  text "4.1" at 273.013,151.782 h1.52
  text "4" at 200.642,148.734 h1.52
  text "Power2" at 211.054,148.734 h1.52
  text "CF-004" at 234.669,148.734 h1.52
  text "2.76mil" at 256.507,148.734 h1.52
  text "Bottom Solder" at 211.054,145.686 h1.52
  text "Solder Resist" at 234.669,145.686 h1.52
  text "0.40mil" at 256.507,145.686 h1.52
  text "3.5" at 273.013,145.686 h1.52
  text "Bottom Overlay" at 211.054,142.638 h1.52
M17 Embedded Cavity:
  text ".Layer_Name" at -34.171,-45.663 h1.52
M18 Embedded Assembly:
  text ".Layer_Name" at -34.171,-45.663 h1.52
M19 Embedded Keepout:
  text ".Layer_Name" at -34.171,-45.663 h1.52

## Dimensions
-48.826,-34.017 to -23.426,-34.017 on M2 Board Dimensions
